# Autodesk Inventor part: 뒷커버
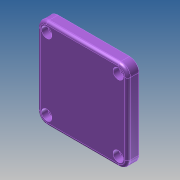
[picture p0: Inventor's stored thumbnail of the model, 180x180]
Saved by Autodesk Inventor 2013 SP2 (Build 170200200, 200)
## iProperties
Created: 2025-06
Part Number: 뒷커버
Material: Generic
Document SubType Name: Modeling
Designer: i
Density: 1 g/cm^3
Author: i
변환 표준: STEP AP214IS
전처리기: Build: 200, Release: 2013 SP2 Update 6 - Date: Thu 07/17/2014
전송 단위: 밀리미터
불확실성: 0.01
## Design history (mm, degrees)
node "뒷커버1"
node "솔리드1"
node "기준1"
